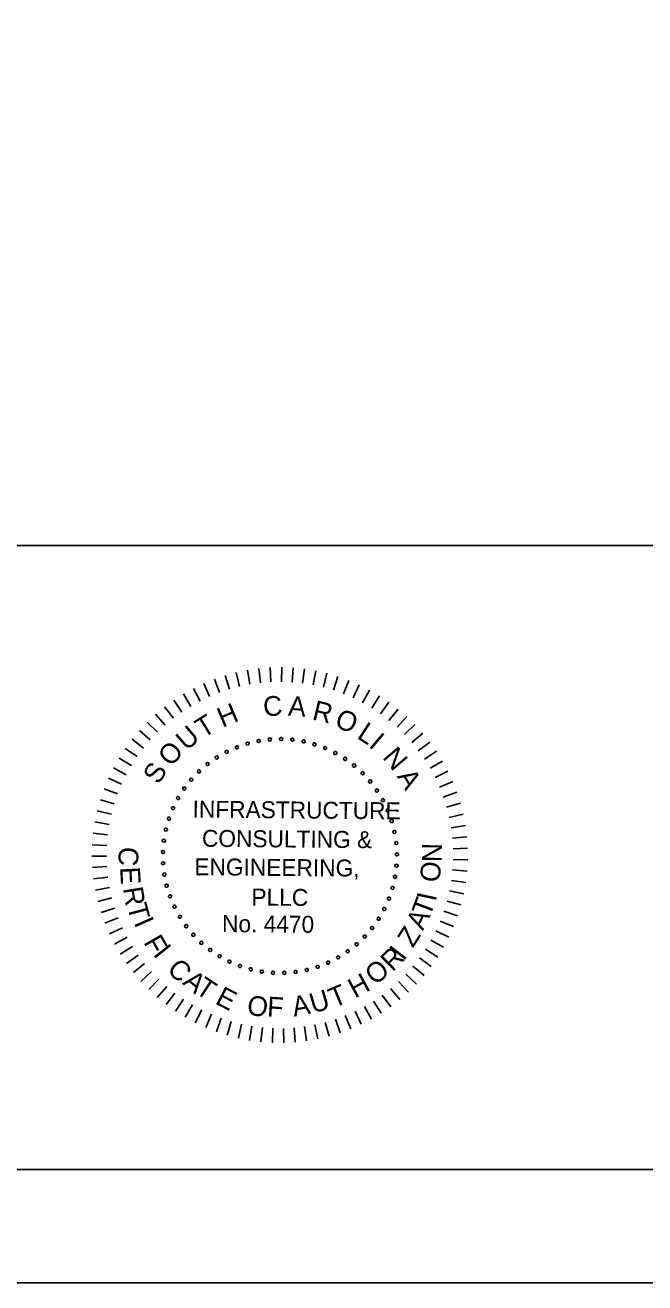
# Model space of a CAD drawing. Extents: x 96 to 240, y 601 to 689.
# Drawn here: x 196.68 to 207.6, y 601 to 623.18 of the extents above; entities that cross this region are included whole.
import ezdxf

# ---------------------------------------------------------------- set-up
doc = ezdxf.new("R2010")
doc.units = 0
for name, color, linetype in [('BR_BORDER LINES', 7, 'Continuous'), ('BR_TEXT', 7, 'Continuous'), ('Level 31', 7, 'Continuous')]:
    doc.layers.add(name, color=color, linetype=linetype)

msp = doc.modelspace()

# ---------------------------------------------------------------- linework, layer by layer
at = {"layer": 'BR_BORDER LINES'}
for p, q in [((186.375, 614.004), (207.836, 614.004)), ((103.173, 603.003), (237.837, 603.003))]:
    msp.add_line(p, q, dxfattribs=at)
at = {"layer": 'BR_TEXT'}
for p, q in [((201, 611.853), (201.013, 611.599)), ((201.202, 611.857), (201.199, 611.602)), ((201.403, 611.849), (201.386, 611.595)), ((200.015, 611.649), (200.104, 611.411)), ((200.206, 611.714), (200.28, 611.47)), ((200.401, 611.767), (200.46, 611.519)), ((200.599, 611.808), (200.643, 611.557)), ((200.798, 611.836), (200.827, 611.583)), ((201.604, 611.829), (201.571, 611.576)), ((201.804, 611.796), (201.755, 611.546)), ((202, 611.752), (201.937, 611.505)), ((202.194, 611.695), (202.116, 611.453)), ((202.384, 611.627), (202.291, 611.39)), ((199.646, 611.485), (199.763, 611.259)), ((199.828, 611.573), (199.931, 611.34)), ((202.57, 611.547), (202.463, 611.316)), ((202.75, 611.456), (202.629, 611.232)), ((199.299, 611.278), (199.443, 611.068)), ((199.469, 611.387), (199.6, 611.169)), ((202.925, 611.354), (202.79, 611.138)), ((203.093, 611.242), (202.945, 611.035)), ((198.981, 611.03), (199.149, 610.839)), ((199.136, 611.159), (199.293, 610.958)), ((203.253, 611.12), (203.093, 610.922)), ((203.406, 610.988), (203.235, 610.8)), ((198.695, 610.745), (198.885, 610.576)), ((198.833, 610.892), (199.013, 610.712)), ((203.551, 610.847), (203.368, 610.67)), ((198.565, 610.59), (198.766, 610.433)), ((203.687, 610.698), (203.493, 610.532)), ((203.813, 610.54), (203.61, 610.387)), ((198.446, 610.428), (198.655, 610.283)), ((203.93, 610.376), (203.718, 610.235)), ((198.237, 610.082), (198.463, 609.964)), ((198.336, 610.258), (198.554, 610.127)), ((204.036, 610.204), (203.816, 610.076)), ((198.149, 609.9), (198.381, 609.796)), ((204.132, 610.026), (203.904, 609.912)), ((198.072, 609.714), (198.31, 609.624)), ((204.217, 609.843), (203.982, 609.743)), ((204.29, 609.655), (204.05, 609.569)), ((198.007, 609.522), (198.25, 609.448)), ((204.352, 609.462), (204.107, 609.392)), ((197.953, 609.328), (198.2, 609.268)), ((204.402, 609.267), (204.153, 609.211)), ((197.911, 609.13), (198.162, 609.086)), ((204.44, 609.068), (204.188, 609.028)), ((197.882, 608.93), (198.135, 608.901)), ((204.465, 608.868), (204.212, 608.843)), ((197.859, 608.527), (198.114, 608.529)), ((197.864, 608.729), (198.119, 608.716)), ((204.479, 608.667), (204.224, 608.657)), ((197.867, 608.326), (198.121, 608.343)), ((204.48, 608.465), (204.225, 608.471)), ((197.886, 608.125), (198.139, 608.157)), ((204.445, 608.062), (204.193, 608.099)), ((204.469, 608.263), (204.215, 608.284)), ((197.918, 607.925), (198.168, 607.973)), ((204.41, 607.864), (204.161, 607.916)), ((197.962, 607.728), (198.209, 607.791)), ((204.362, 607.667), (204.117, 607.735)), ((198.018, 607.534), (198.26, 607.612)), ((198.086, 607.344), (198.323, 607.437)), ((204.303, 607.474), (204.062, 607.557)), ((198.165, 607.158), (198.396, 607.265)), ((204.149, 607.101), (203.92, 607.212)), ((204.231, 607.285), (203.996, 607.382)), ((198.255, 606.977), (198.479, 607.098)), ((204.055, 606.922), (203.833, 607.047)), ((198.356, 606.802), (198.572, 606.937)), ((198.468, 606.634), (198.675, 606.782)), ((203.951, 606.749), (203.737, 606.887)), ((198.589, 606.473), (198.787, 606.633)), ((203.712, 606.424), (203.516, 606.587)), ((203.836, 606.583), (203.631, 606.734)), ((198.72, 606.319), (198.909, 606.491)), ((198.861, 606.174), (199.038, 606.357)), ((203.434, 606.131), (203.26, 606.316)), ((203.577, 606.273), (203.392, 606.448)), ((199.01, 606.038), (199.176, 606.231)), ((199.167, 605.911), (199.32, 606.114)), ((203.124, 605.873), (202.973, 606.079)), ((203.283, 605.997), (203.12, 606.193)), ((199.331, 605.794), (199.472, 606.005)), ((199.502, 605.687), (199.63, 605.907)), ((202.784, 605.655), (202.659, 605.878)), ((202.957, 605.759), (202.819, 605.973)), ((199.68, 605.59), (199.794, 605.818)), ((199.863, 605.505), (199.963, 605.739)), ((200.051, 605.431), (200.136, 605.671)), ((202.231, 605.41), (202.149, 605.651)), ((202.42, 605.481), (202.323, 605.716)), ((202.604, 605.562), (202.494, 605.792)), ((200.243, 605.368), (200.314, 605.613)), ((200.438, 605.318), (200.494, 605.566)), ((200.636, 605.279), (200.677, 605.53)), ((200.836, 605.253), (200.862, 605.506)), ((201.038, 605.238), (201.048, 605.493)), ((201.24, 605.236), (201.234, 605.491)), ((201.441, 605.247), (201.42, 605.501)), ((201.642, 605.269), (201.606, 605.522)), ((201.841, 605.304), (201.789, 605.554)), ((202.037, 605.351), (201.97, 605.597))]:
    msp.add_line(p, q, dxfattribs=at)
for centre, start, end in [((200.601, 610.512), 16.1422, 196.1422), ((200.601, 610.512), 196.1422, 16.1422), ((200.795, 610.558), 10.6038, 190.6038), ((200.795, 610.558), 190.6038, 10.6038), ((200.993, 610.585), 5.0653, 185.0653), ((200.993, 610.585), 185.0653, 5.0653), ((201.192, 610.593), 359.5268, 179.5268), ((201.192, 610.593), 179.5268, 359.5268), ((201.391, 610.581), 353.9884, 173.9884), ((201.391, 610.581), 173.9884, 353.9884), ((201.588, 610.55), 348.4499, 168.4499), ((201.588, 610.55), 168.4499, 348.4499), ((201.781, 610.5), 342.9114, 162.9114), ((200.058, 610.267), 32.7576, 212.7576), ((200.231, 610.366), 27.2191, 207.2191), ((200.231, 610.366), 207.2191, 27.2191), ((200.412, 610.448), 21.6807, 201.6807), ((200.412, 610.448), 201.6807, 21.6807), ((201.781, 610.5), 162.9114, 342.9114), ((201.968, 610.432), 157.373, 337.373), ((201.968, 610.432), 337.373, 157.373), ((202.148, 610.346), 151.8345, 331.8345), ((202.148, 610.346), 331.8345, 151.8345), ((199.896, 610.151), 38.2961, 218.2961), ((199.896, 610.151), 218.2961, 38.2961), ((200.058, 610.267), 212.7576, 32.7576), ((202.319, 610.244), 146.2961, 326.2961), ((202.319, 610.244), 326.2961, 146.2961), ((202.479, 610.125), 140.7576, 320.7576), ((202.479, 610.125), 320.7576, 140.7576), ((199.608, 609.876), 49.373, 229.373), ((199.608, 609.876), 229.373, 49.373), ((199.745, 610.021), 43.8345, 223.8345), ((199.745, 610.021), 223.8345, 43.8345), ((202.627, 609.991), 135.2191, 315.2191), ((202.627, 609.991), 315.2191, 135.2191), ((202.761, 609.844), 129.6807, 309.6807), ((202.761, 609.844), 309.6807, 129.6807), ((199.485, 609.719), 54.9114, 234.9114), ((199.485, 609.719), 234.9114, 54.9114), ((202.88, 609.684), 124.1422, 304.1422), ((202.88, 609.684), 304.1422, 124.1422), ((199.378, 609.551), 60.4499, 240.4499), ((199.378, 609.551), 240.4499, 60.4499), ((202.984, 609.514), 118.6038, 298.6038), ((202.984, 609.514), 298.6038, 118.6038), ((199.216, 609.187), 71.5268, 251.5268), ((199.216, 609.187), 251.5268, 71.5268), ((199.288, 609.373), 65.9884, 245.9884), ((199.288, 609.373), 245.9884, 65.9884), ((203.07, 609.334), 113.0653, 293.0653), ((203.07, 609.334), 293.0653, 113.0653), ((199.161, 608.996), 77.0653, 257.0653), ((199.161, 608.996), 257.0653, 77.0653), ((203.139, 609.147), 107.5268, 287.5268), ((203.139, 609.147), 287.5268, 107.5268), ((203.189, 608.954), 101.9884, 281.9884), ((203.189, 608.954), 281.9884, 101.9884), ((199.126, 608.799), 82.6038, 262.6038), ((199.126, 608.799), 262.6038, 82.6038), ((203.221, 608.758), 96.4499, 276.4499), ((203.221, 608.758), 276.4499, 96.4499), ((199.109, 608.601), 88.1422, 268.1422), ((199.109, 608.601), 268.1422, 88.1422), ((203.233, 608.559), 90.9114, 270.9114), ((203.233, 608.559), 270.9114, 90.9114), ((199.112, 608.402), 93.6807, 273.6807), ((199.112, 608.402), 273.6807, 93.6807), ((203.226, 608.359), 85.373, 265.373), ((203.226, 608.359), 265.373, 85.373), ((199.134, 608.203), 99.2191, 279.2191), ((199.134, 608.203), 279.2191, 99.2191), ((203.2, 608.162), 79.8345, 259.8345), ((203.2, 608.162), 259.8345, 79.8345), ((199.175, 608.008), 104.7576, 284.7576), ((199.175, 608.008), 284.7576, 104.7576), ((203.155, 607.968), 74.2961, 254.2961), ((203.155, 607.968), 254.2961, 74.2961), ((199.235, 607.818), 110.2961, 290.2961), ((199.235, 607.818), 290.2961, 110.2961), ((199.312, 607.635), 115.8345, 295.8345), ((199.312, 607.635), 295.8345, 115.8345), ((203.092, 607.779), 68.7576, 248.7576), ((203.092, 607.779), 248.7576, 68.7576), ((199.407, 607.459), 121.373, 301.373), ((199.407, 607.459), 301.373, 121.373), ((202.912, 607.424), 57.6807, 237.6807), ((202.912, 607.424), 237.6807, 57.6807), ((203.01, 607.597), 63.2191, 243.2191), ((203.01, 607.597), 243.2191, 63.2191), ((199.519, 607.294), 126.9114, 306.9114), ((199.519, 607.294), 306.9114, 126.9114), ((202.797, 607.261), 52.1422, 232.1422), ((202.797, 607.261), 232.1422, 52.1422), ((199.646, 607.141), 132.4499, 312.4499), ((199.646, 607.141), 312.4499, 132.4499), ((199.787, 607), 137.9884, 317.9884), ((199.787, 607), 317.9884, 137.9884), ((202.523, 606.972), 41.0653, 221.0653), ((202.523, 606.972), 221.0653, 41.0653), ((202.667, 607.11), 46.6038, 226.6038), ((202.667, 607.11), 226.6038, 46.6038), ((199.941, 606.874), 143.5268, 323.5268), ((199.941, 606.874), 323.5268, 143.5268), ((200.107, 606.763), 149.0653, 329.0653), ((200.107, 606.763), 329.0653, 149.0653), ((202.198, 606.741), 29.9884, 209.9884), ((202.198, 606.741), 209.9884, 29.9884), ((202.366, 606.849), 35.5268, 215.5268), ((202.366, 606.849), 215.5268, 35.5268), ((200.282, 606.668), 154.6038, 334.6038), ((200.282, 606.668), 334.6038, 154.6038), ((200.466, 606.591), 160.1422, 340.1422), ((200.466, 606.591), 340.1422, 160.1422), ((200.657, 606.532), 345.6807, 165.6807), ((200.657, 606.532), 165.6807, 345.6807), ((200.852, 606.492), 351.2191, 171.2191), ((201.644, 606.522), 13.373, 193.373), ((201.644, 606.522), 193.373, 13.373), ((201.835, 606.577), 18.9114, 198.9114), ((201.835, 606.577), 198.9114, 18.9114), ((202.021, 606.65), 24.4499, 204.4499), ((202.021, 606.65), 204.4499, 24.4499), ((200.852, 606.492), 171.2191, 351.2191), ((201.05, 606.471), 356.7576, 176.7576), ((201.05, 606.471), 176.7576, 356.7576), ((201.249, 606.469), 2.2961, 182.2961), ((201.249, 606.469), 182.2961, 2.2961), ((201.448, 606.486), 7.8345, 187.8345), ((201.448, 606.486), 187.8345, 7.8345)]:
    msp.add_arc(centre, 0.028, start, end, dxfattribs=at)
at = {"layer": 'Level 31'}
msp.add_lwpolyline([(95.84, 689.004), (95.84, 601.004), (239.84, 601.004), (239.84, 689.004)], dxfattribs=at)

# ---------------------------------------------------------------- texts
at = {"layer": 'BR_TEXT'}
for s, height, rotation, p in [('H', 0.349, 22.7882, (200.158, 610.789)), ('C', 0.349, 4.7281, (200.89, 610.987)), ('A', 0.349, 355.6981, (201.308, 611.007)), ('R', 0.349, 346.6681, (201.725, 610.939)), ('T', 0.349, 31.8182, (199.819, 610.599)), ('O', 0.349, 337.638, (202.116, 610.819)), ('U', 0.349, 40.8482, (199.526, 610.374)), ('L', 0.349, 327.108, (202.511, 610.618)), ('O', 0.349, 49.8782, (199.258, 610.09)), ('I', 0.349, 319.578, (202.721, 610.466)), ('N', 0.349, 310.548, (202.965, 610.263)), ('S', 0.349, 58.9083, (199.036, 609.777)), ('A', 0.349, 301.5179, (203.225, 609.934)), ('INFRASTRUCTURE', 0.29909, 359.5268, (199.631, 609.207)), ('CONSULTING &', 0.29909, 359.5268, (199.796, 608.693)), ('C', 0.349, 267.025, (198.336, 608.698)), ('N', 0.349, 89.2085, (204.022, 608.419)), ('E', 0.349, 273.025, (198.354, 608.331)), ('ENGINEERING,', 0.29909, 359.5268, (199.662, 608.191)), ('O', 0.349, 83.2085, (203.978, 608.053)), ('R', 0.349, 279.025, (198.405, 607.962)), ('PLLC', 0.2991, 359.5268, (200.668, 607.657)), ('I', 0.349, 77.9093, (203.916, 607.716)), ('T', 0.349, 285.025, (198.475, 607.647)), ('T', 0.349, 69.3954, (203.813, 607.446)), ('I', 0.349, 293.7713, (198.593, 607.355)), ('No. 4470', 0.2991, 359.5268, (200.15, 607.189)), ('A', 0.349, 63.3954, (203.69, 607.204)), ('Z', 0.349, 57.3954, (203.514, 606.899)), ('F', 0.349, 299.7713, (198.758, 607.01)), ('I', 0.349, 308.5268, (198.927, 606.795)), ('R', 0.349, 44.5268, (203.153, 606.479)), ('I', 0.349, 52.3339, (203.35, 606.668)), ('C', 0.349, 314.5268, (199.164, 606.515)), ('O', 0.349, 38.5268, (202.846, 606.239)), ('A', 0.349, 320.5268, (199.441, 606.28)), ('T', 0.349, 326.5268, (199.658, 606.126)), ('H', 0.349, 28.5268, (202.494, 606.015)), ('E', 0.349, 332.5268, (200.013, 605.935)), ('U', 0.349, 16.5268, (201.754, 605.751)), ('T', 0.349, 22.5268, (202.121, 605.848)), ('O', 0.349, 350.5268, (200.573, 605.74)), ('F', 0.349, 356.5268, (200.939, 605.703)), ('A', 0.349, 10.5268, (201.419, 605.697))]:
    msp.add_text(s, height=height, rotation=rotation, dxfattribs=at).set_placement(p)

doc.saveas('drawing.dxf')
